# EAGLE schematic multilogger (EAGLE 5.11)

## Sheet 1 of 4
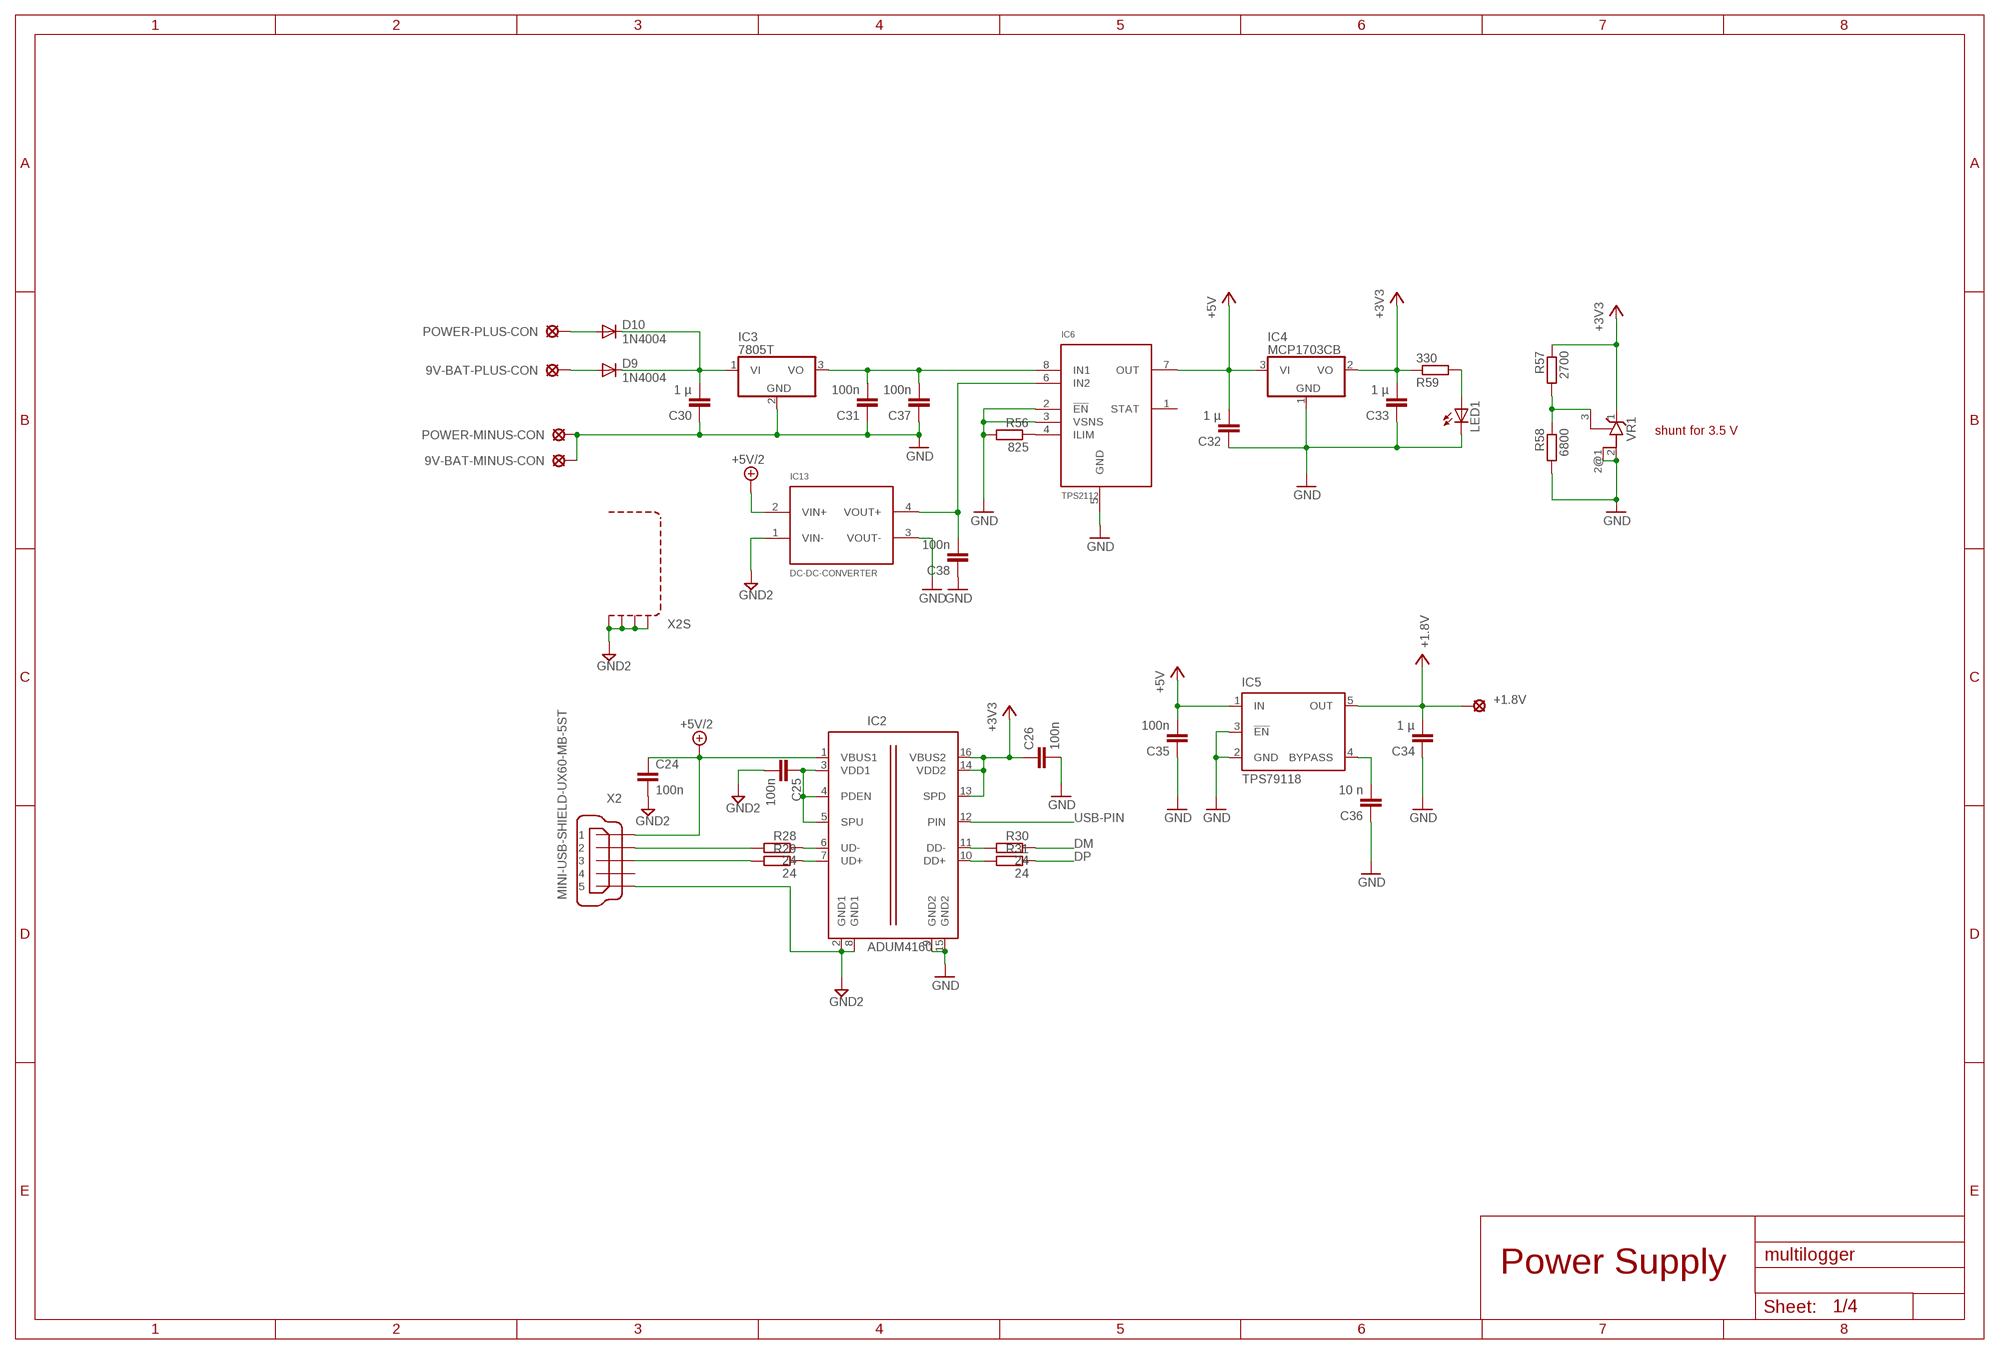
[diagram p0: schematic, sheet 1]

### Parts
9V-BAT-MINUS-CON  LSP10  [LSP10]
9V-BAT-PLUS-CON  LSP10  [LSP10]
+1.8V  LSP10  [LSP10]
C24  100n  C-EUC0805  [C0805]
C25  100n  C-EUC0805  [C0805]
C26  100n  C-EUC0805  [C0805]
C30  1 µ  C-EUC0805  [C0805]
C31  100n  C-EUC0805  [C0805]
C32  1 µ  C-EUC0805  [C0805]
C33  1 µ  C-EUC0805  [C0805]
C34  1 µ  C-EUC0805  [C0805]
C35  100n  C-EUC0805  [C0805]
C36  10 n  C-EUC0805  [C0805]
C37  100n  C-EUC0805  [C0805]
C38  100n  C-EUC0805  [C0805]
D9  1N4004  [DO41-10]
D10  1N4004  [DO41-10]
IC2  ADUM4160  [SO-16W]
IC3  7805T  [TO220H]
IC4  MCP1703CB  [SOT23]
IC5  TPS79118  [SOT23-DBV]
IC6  TPS2112  [TSSOP8]
IC13  DC-DC-CONVERTER  [DC-DC-CONVERTER]
LED1  LED5MM  [LED5MM]
POWER-MINUS-CON  LSP10  [LSP10]
POWER-PLUS-CON  LSP10  [LSP10]
R28  24  R-EU_R0805  [R0805]
R29  24  R-EU_R0805  [R0805]
R30  24  R-EU_R0805  [R0805]
R31  24  R-EU_R0805  [R0805]
R56  825  R-EU_R0805  [R0805]
R57  2700  R-EU_R0805  [R0805]
R58  6800  R-EU_R0805  [R0805]
R59  330  R-EU_R0805  [R0805]
VR1  TL431CLPSO89-3  [SOT89]
X2  MINI-USB-SHIELD-UX60-MB-5ST  [TYCO]

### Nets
+1.8V: +1.8V.MP C34.2 IC5.5(OUT) ; also sheet 4
+3V3: C26.1 C33.2 IC2.13(SPD) IC2.14(VDD2) IC2.16(VBUS2) IC4.2(VO) R57.1 R59.1 VR1.1(C) ; also sheet 2,3,4
+5V: C32.2 C35.2 IC4.3(VI) IC5.1(IN) IC6.7(OUT) ; also sheet 2
+5V/2: C24.1 IC2.1(VBUS1) IC13.2(VIN+) X2.1
DM: R30.1 ; also sheet 2
DP: R31.1 ; also sheet 2
GND: 9V-BAT-MINUS-CON.MP C26.2 C30.1 C31.1 C32.1 C33.1 C34.1 C35.1 C36.1 C37.1 C38.1 IC2.9(GND2) IC2.15(GND2) IC3.2(GND) IC4.1(GND) IC5.2(GND) IC5.3(!EN) IC6.2(!EN) IC6.3(VSNS) IC6.5(GND) IC13.3(VOUT-) LED1.K(C) POWER-MINUS-CON.MP R56.2 R58.2 VR1.2(A) VR1.2@1(A1) ; also sheet 2,3,4
GND2: C24.2 C25.2 IC2.2(GND1) IC2.8(GND1) IC13.1(VIN-) X2.5 X2.M1(S1) X2.M2(S2) X2.M3(S3) X2.M4(S4)
N$20: LED1.A R59.2
N$38: R28.2 X2.2
N$41: R29.2 X2.3
N$43: C25.1 IC2.3(VDD1) IC2.4(PDEN) IC2.5(SPU)
N$53: IC2.6(UD-) R28.1
N$54: IC2.7(UD+) R29.1
N$57: IC2.11(DD-) R30.2
N$59: IC2.10(DD+) R31.2
N$101: 9V-BAT-PLUS-CON.MP D9.A
N$102: D10.A POWER-PLUS-CON.MP
N$104: C36.2 IC5.4(BYPASS)
N$105: C30.2 D9.C D10.C IC3.1(VI)
N$106: C31.2 C37.2 IC3.3(VO) IC6.8(IN1)
N$108: C38.2 IC6.6(IN2) IC13.4(VOUT+)
N$109: IC6.4(ILIM) R56.1
N$110: R57.2 R58.1 VR1.3(R)
USB-PIN: IC2.12(PIN) ; also sheet 2
Unconnected: IC6.1(STAT) X2.4

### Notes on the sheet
- shunt for 3.5 V
- Power Supply

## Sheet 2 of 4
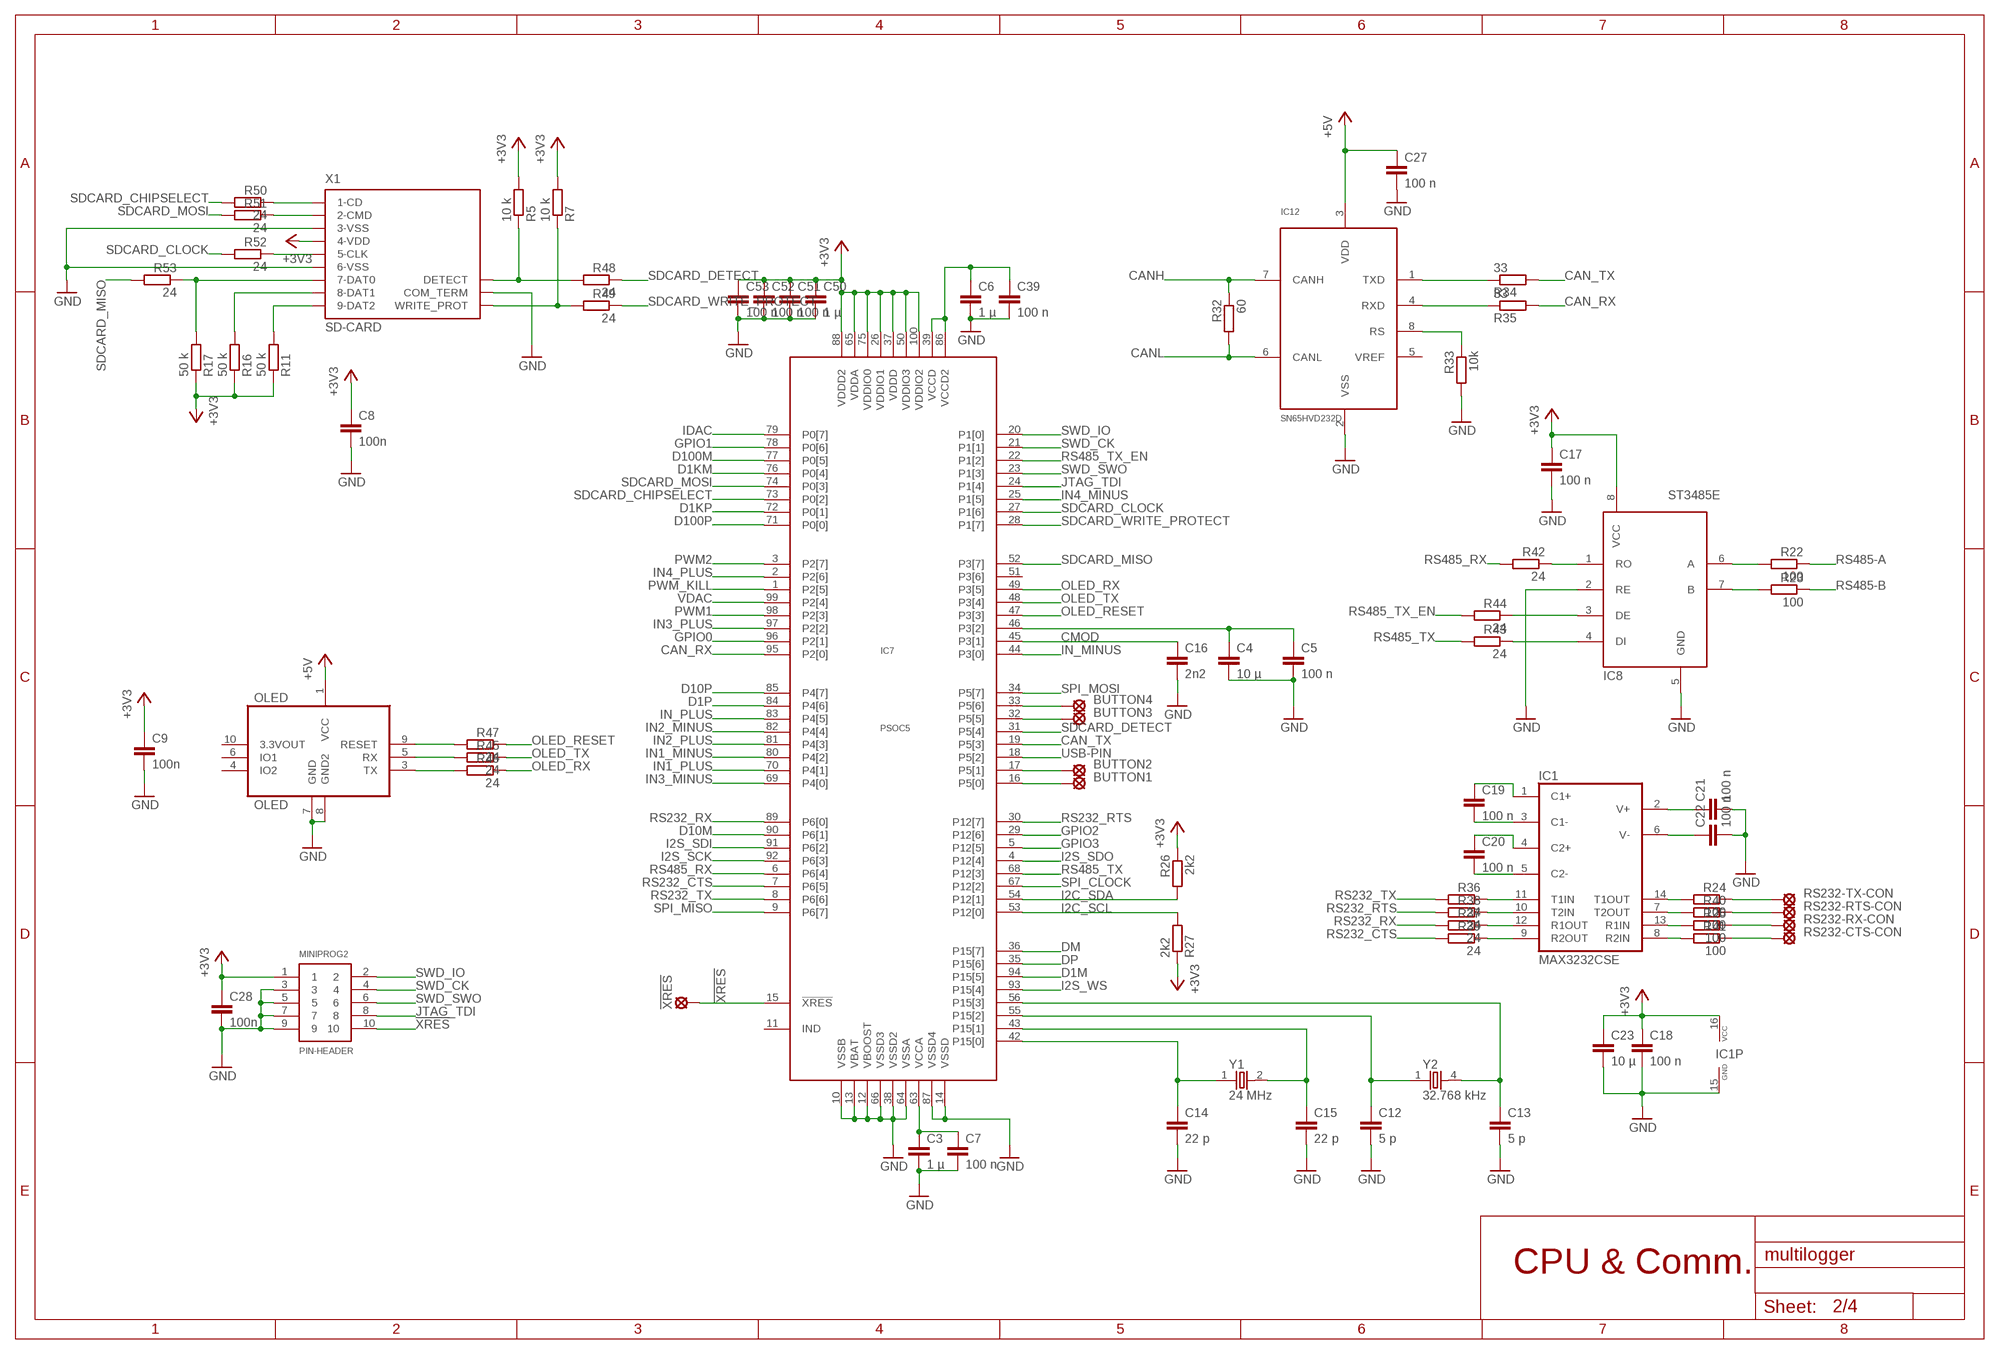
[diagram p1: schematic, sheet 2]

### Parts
!XRES  LSP10  [LSP10]
BUTTON1  LSP10  [LSP10]
BUTTON2  LSP10  [LSP10]
BUTTON3  LSP10  [LSP10]
BUTTON4  LSP10  [LSP10]
C3  1 µ  C-EUC0805  [C0805]
C4  10 µ  C-EUC0805  [C0805]
C5  100 n  C-EUC0805  [C0805]
C6  1 µ  C-EUC0805  [C0805]
C7  100 n  C-EUC0805  [C0805]
C8  100n  C-EUC0805  [C0805]
C9  100n  C-EUC0805  [C0805]
C12  5 p  C-EUC0805  [C0805]
C13  5 p  C-EUC0805  [C0805]
C14  22 p  C-EUC0805  [C0805]
C15  22 p  C-EUC0805  [C0805]
C16  2n2  C-EUC0805  [C0805]
C17  100 n  C-EUC0805  [C0805]
C18  100 n  C-EUC0805  [C0805]
C19  100 n  C-EUC0805  [C0805]
C20  100 n  C-EUC0805  [C0805]
C21  100 n  C-EUC0805  [C0805]
C22  100 n  C-EUC0805  [C0805]
C23  10 µ  C-EUC0805  [C0805]
C27  100 n  C-EUC0805  [C0805]
C28  100n  C-EUC0805  [C0805]
C39  100 n  C-EUC0805  [C0805]
C50  1 µ  C-EUC0805  [C0805]
C51  100 n  C-EUC0805  [C0805]
C52  100 n  C-EUC0805  [C0805]
C53  100 n  C-EUC0805  [C0805]
IC1  MAX3232CSE  [SO16]
IC7  PSOC5  [TQFP100]
IC8  ST3485E  [SO08]
IC12  SN65HVD232D  MCP2551SOIC8  [SOIC8]
MINIPROG2  PIN-HEADER  [PIN-HEADER-50-MIL-2X5]
OLED  OLED  [MA05-2]
R5  10 k  R-EU_R0805  [R0805]
R7  10 k  R-EU_R0805  [R0805]
R11  50 k  R-EU_R0805  [R0805]
R16  50 k  R-EU_R0805  [R0805]
R17  50 k  R-EU_R0805  [R0805]
R22  100  R-EU_R0805  [R0805]
R23  100  R-EU_R0805  [R0805]
R24  100  R-EU_R0805  [R0805]
R25  100  R-EU_R0805  [R0805]
R26  2k2  R-EU_R0805  [R0805]
R27  2k2  R-EU_R0805  [R0805]
R32  60  R-EU_0207/5V  [0207/5V]
R33  10k  R-EU_R0805  [R0805]
R34  33  R-EU_R0805  [R0805]
R35  33  R-EU_R0805  [R0805]
R36  24  R-EU_R0805  [R0805]
R37  24  R-EU_R0805  [R0805]
R38  24  R-EU_R0805  [R0805]
R39  24  R-EU_R0805  [R0805]
R40  100  R-EU_R0805  [R0805]
R41  100  R-EU_R0805  [R0805]
R42  24  R-EU_R0805  [R0805]
R43  24  R-EU_R0805  [R0805]
R44  24  R-EU_R0805  [R0805]
R45  24  R-EU_R0805  [R0805]
R46  24  R-EU_R0805  [R0805]
R47  24  R-EU_R0805  [R0805]
R48  24  R-EU_R0805  [R0805]
R49  24  R-EU_R0805  [R0805]
R50  24  R-EU_R0805  [R0805]
R51  24  R-EU_R0805  [R0805]
R52  24  R-EU_R0805  [R0805]
R53  24  R-EU_R0805  [R0805]
RS232-CTS-CON  LSP10  [LSP10]
RS232-RTS-CON  LSP10  [LSP10]
RS232-RX-CON  LSP10  [LSP10]
RS232-TX-CON  LSP10  [LSP10]
X1  SD-CARD  FPS009-3000  [FPS009-3000]
Y1  24 MHz  ECS-CRYSTAL  [ECS-CRYSTAL]
Y2  32.768 kHz  ABS25-CRYSTAL  [ABS25-CRYSTAL]

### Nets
!XRES: !XRES.MP IC7.15(!XRES) MINIPROG2.10
+3V3: C8.1 C9.1 C17.1 C18.1 C23.1 C28.1 C50.1 C51.1 C52.1 C53.1 IC1.16(VCC) IC7.26(VDDIO1) IC7.37(VDDD) IC7.50(VDDIO3) IC7.65(VDDA) IC7.75(VDDIO0) IC7.88(VDDD2) IC7.100(VDDIO2) IC8.8(VCC) MINIPROG2.1 R5.2 R7.2 R11.1 R16.1 R17.1 R26.1 R27.1 X1.4(4-VDD) ; also sheet 1,3,4
+5V: C27.1 IC12.3(VDD) OLED.1(VCC) ; also sheet 1
CAN_RX: IC7.95(P2[0]) R35.2
CAN_TX: IC7.19(P5[3]) R34.2
CANH: IC12.7(CANH) R32.1 ; also sheet 4
CANL: IC12.6(CANL) R32.2 ; also sheet 4
CMOD: C16.1 IC7.45(P3[1])
D1KM: IC7.76(P0[4]) ; also sheet 3
D1KP: IC7.72(P0[1]) ; also sheet 3
D1M: IC7.94(P15[5]) ; also sheet 3
D1P: IC7.84(P4[6]) ; also sheet 3
D10M: IC7.90(P6[1]) ; also sheet 3
D10P: IC7.85(P4[7]) ; also sheet 3
D100M: IC7.77(P0[5]) ; also sheet 3
D100P: IC7.71(P0[0]) ; also sheet 3
DM: IC7.36(P15[7]) ; also sheet 1
DP: IC7.35(P15[6]) ; also sheet 1
GND: C3.2 C4.2 C5.2 C6.2 C7.2 C8.2 C9.2 C12.2 C13.2 C14.2 C15.2 C16.2 C17.2 C18.2 C21.2 C22.2 C23.2 C27.2 C28.2 C39.2 C50.2 C51.2 C52.2 C53.2 IC1.15(GND) IC7.10(VSSB) IC7.12(VBOOST) IC7.13(VBAT) IC7.14(VSSD) IC7.38(VSSD2) IC7.64(VSSA) IC7.66(VSSD3) IC7.87(VSSD4) IC8.2(RE) IC8.5(GND) IC12.2(VSS) MINIPROG2.3 MINIPROG2.5 MINIPROG2.7 MINIPROG2.9 OLED.7(GND) OLED.8(GND2) R33.2 X1.3(3-VSS) X1.6(6-VSS) X1.COM_TERM ; also sheet 1,3,4
GPIO0: IC7.96(P2[1]) ; also sheet 4
GPIO1: IC7.78(P0[6]) ; also sheet 4
GPIO2: IC7.29(P12[6]) ; also sheet 4
GPIO3: IC7.5(P12[5]) ; also sheet 4
I2C_SCL: IC7.53(P12[0]) R27.2 ; also sheet 4
I2C_SDA: IC7.54(P12[1]) R26.2 ; also sheet 4
I2S_SCK: IC7.92(P6[3]) ; also sheet 4
I2S_SDI: IC7.91(P6[2]) ; also sheet 4
I2S_SDO: IC7.4(P12[4]) ; also sheet 4
I2S_WS: IC7.93(P15[4]) ; also sheet 4
IDAC: IC7.79(P0[7]) ; also sheet 4
IN1_MINUS: IC7.80(P4[2]) ; also sheet 3
IN1_PLUS: IC7.70(P4[1]) ; also sheet 3
IN2_MINUS: IC7.82(P4[4]) ; also sheet 3
IN2_PLUS: IC7.81(P4[3]) ; also sheet 3
IN3_MINUS: IC7.69(P4[0]) ; also sheet 3
IN3_PLUS: IC7.97(P2[2]) ; also sheet 3
IN4_MINUS: IC7.25(P1[5]) ; also sheet 3
IN4_PLUS: IC7.2(P2[6]) ; also sheet 3
IN_MINUS: IC7.44(P3[0]) ; also sheet 3
IN_PLUS: IC7.83(P4[5]) ; also sheet 3
JTAG_TDI: IC7.24(P1[4]) MINIPROG2.8
N$3: IC12.8(RS) R33.1
N$7: IC8.6(A) R22.2
N$8: IC8.7(B) R23.2
N$9: R11.2 X1.9(9-DAT2)
N$13: C19.1 IC1.1(C1+)
N$14: IC12.1(TXD) R34.1
N$15: IC12.4(RXD) R35.1
N$16: C3.1 C7.1 IC7.63(VCCA)
N$18: C19.2 IC1.3(C1-)
N$21: C4.1 C5.1 IC7.46(P3[2])
N$22: C6.1 C39.1 IC7.39(VCCD) IC7.86(VCCD2)
N$23: IC1.10(T2IN) R38.1
N$24: R16.2 X1.8(8-DAT1)
N$27: C20.1 IC1.4(C2+)
N$28: C20.2 IC1.5(C2-)
N$31: C21.1 IC1.2(V+)
N$32: C22.1 IC1.6(V-)
N$33: IC1.14(T1OUT) R24.2
N$34: IC1.13(R1IN) R25.2
N$35: R24.1 RS232-TX-CON.MP
N$36: R25.1 RS232-RX-CON.MP
N$37: IC1.11(T1IN) R36.1
N$39: IC1.12(R1OUT) R37.1
N$40: IC1.9(R2OUT) R39.1
N$44: IC1.7(T2OUT) R40.2
N$45: IC1.8(R2IN) R41.2
N$46: BUTTON4.MP IC7.33(P5[6])
N$47: BUTTON3.MP IC7.32(P5[5])
N$48: R40.1 RS232-RTS-CON.MP
N$49: R41.1 RS232-CTS-CON.MP
N$50: IC8.4(DI) R43.1
N$51: BUTTON2.MP IC7.17(P5[1])
N$52: BUTTON1.MP IC7.16(P5[0])
N$55: IC8.1(RO) R42.1
N$56: IC8.3(DE) R44.1
N$58: OLED.5(RX) R45.2
N$60: R17.2 R53.1 X1.7(7-DAT0)
N$61: OLED.9(RESET) R47.2
N$62: OLED.3(TX) R46.2
N$63: R52.1 X1.5(5-CLK)
N$64: R51.1 X1.2(2-CMD)
N$65: R50.1 X1.1(1-CD)
N$66: R5.1 R48.2 X1.DETECT
N$67: R7.1 R49.2 X1.WRITE_PROT
N$73: C13.1 IC7.56(P15[3]) Y2.4
N$74: C12.1 IC7.55(P15[2]) Y2.1
N$75: C15.1 IC7.43(P15[1]) Y1.2
N$76: C14.1 IC7.42(P15[0]) Y1.1
OLED_RESET: IC7.47(P3[3]) R47.1
OLED_RX: IC7.49(P3[5]) R46.1
OLED_TX: IC7.48(P3[4]) R45.1
PWM1: IC7.98(P2[3]) ; also sheet 4
PWM2: IC7.3(P2[7]) ; also sheet 4
PWM_KILL: IC7.1(P2[5]) ; also sheet 4
RS232_CTS: IC7.7(P6[5]) R39.2
RS232_RTS: IC7.30(P12[7]) R38.2
RS232_RX: IC7.89(P6[0]) R37.2
RS232_TX: IC7.8(P6[6]) R36.2
RS485-A: R22.1 ; also sheet 4
RS485-B: R23.1 ; also sheet 4
RS485_RX: IC7.6(P6[4]) R42.2
RS485_TX: IC7.68(P12[3]) R43.2
RS485_TX_EN: IC7.22(P1[2]) R44.2
SDCARD_CHIPSELECT: IC7.73(P0[2]) R50.2
SDCARD_CLOCK: IC7.27(P1[6]) R52.2
SDCARD_DETECT: IC7.31(P5[4]) R48.1
SDCARD_MISO: IC7.52(P3[7]) R53.2
SDCARD_MOSI: IC7.74(P0[3]) R51.2
SDCARD_WRITE_PROTECT: IC7.28(P1[7]) R49.1
SPI_CLOCK: IC7.67(P12[2]) ; also sheet 4
SPI_MISO: IC7.9(P6[7]) ; also sheet 4
SPI_MOSI: IC7.34(P5[7]) ; also sheet 4
SWD_CK: IC7.21(P1[1]) MINIPROG2.4
SWD_IO: IC7.20(P1[0]) MINIPROG2.2
SWD_SWO: IC7.23(P1[3]) MINIPROG2.6
USB-PIN: IC7.18(P5[2]) ; also sheet 1
VDAC: IC7.99(P2[4]) ; also sheet 4
Unconnected: IC7.11(IND) IC7.51(P3[6]) IC12.5(VREF) OLED.4(IO2) OLED.6(IO1) OLED.10(3.3VOUT)

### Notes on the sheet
- CPU & Comm.

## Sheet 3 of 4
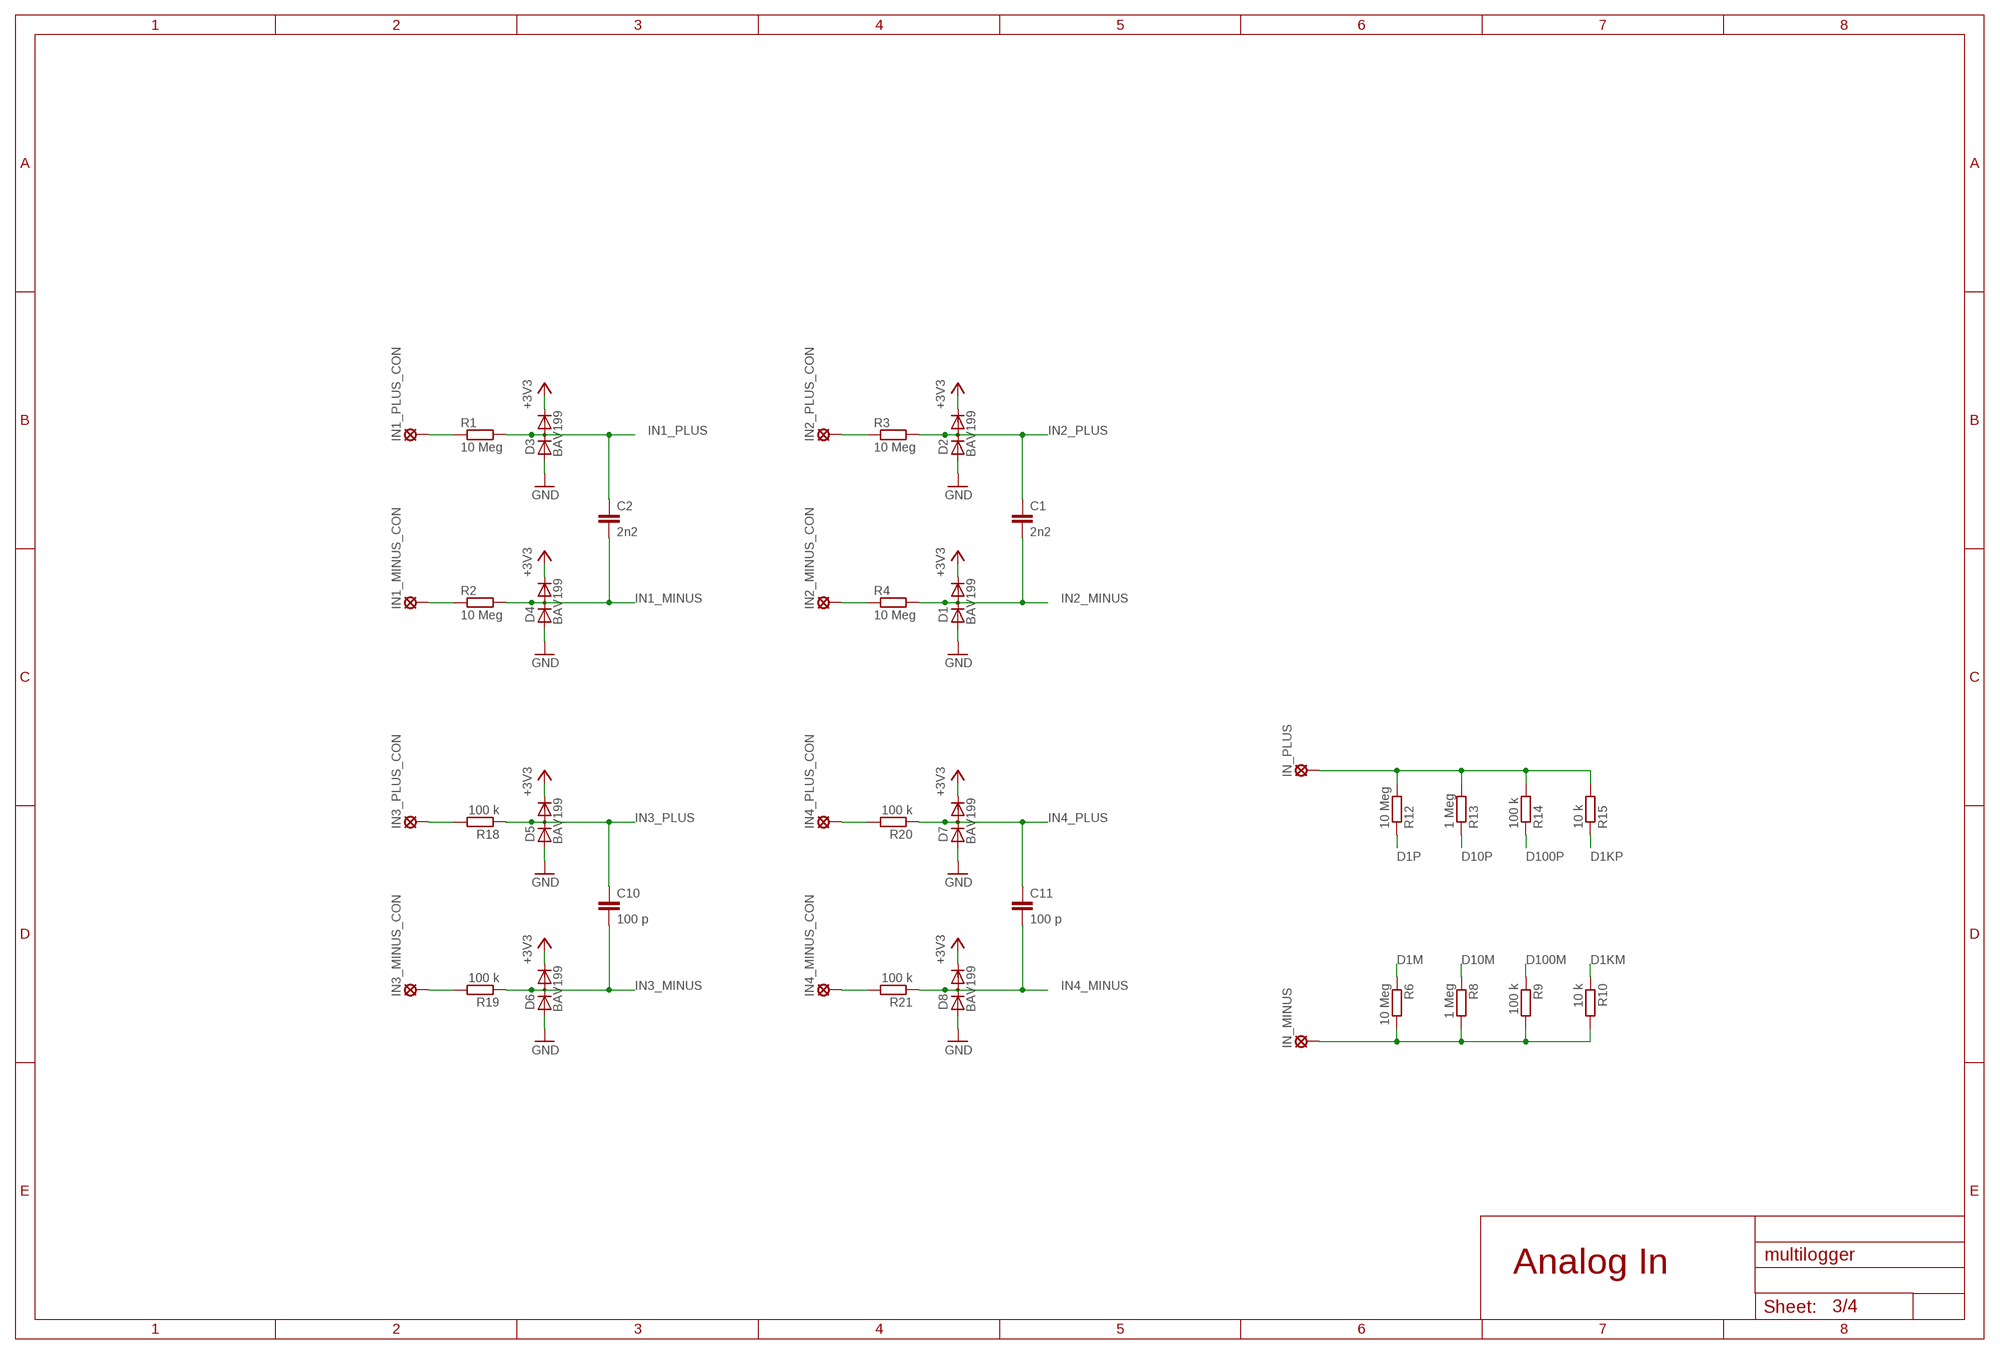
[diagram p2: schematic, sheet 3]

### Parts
C1  2n2  C-EUC0805  [C0805]
C2  2n2  C-EUC0805  [C0805]
C10  100 p  C-EUC0805  [C0805]
C11  100 p  C-EUC0805  [C0805]
D1  BAV199  [SOT23]
D2  BAV199  [SOT23]
D3  BAV199  [SOT23]
D4  BAV199  [SOT23]
D5  BAV199  [SOT23]
D6  BAV199  [SOT23]
D7  BAV199  [SOT23]
D8  BAV199  [SOT23]
IN1_MINUS_CON  LSP10  [LSP10]
IN1_PLUS_CON  LSP10  [LSP10]
IN2_MINUS_CON  LSP10  [LSP10]
IN2_PLUS_CON  LSP10  [LSP10]
IN3_MINUS_CON  LSP10  [LSP10]
IN3_PLUS_CON  LSP10  [LSP10]
IN4_MINUS_CON  LSP10  [LSP10]
IN4_PLUS_CON  LSP10  [LSP10]
IN_MINUS  LSP10  [LSP10]
IN_PLUS  LSP10  [LSP10]
R1  10 Meg  R-EU_0207/15  [0207/35]
R2  10 Meg  R-EU_0207/15  [0207/35]
R3  10 Meg  R-EU_0207/15  [0207/35]
R4  10 Meg  R-EU_0207/15  [0207/35]
R6  10 Meg  R-EU_R1206  [R1206]
R8  1 Meg  R-EU_R1206  [R1206]
R9  100 k  R-EU_R1206  [R1206]
R10  10 k  R-EU_R1206  [R1206]
R12  10 Meg  R-EU_R1206  [R1206]
R13  1 Meg  R-EU_R1206  [R1206]
R14  100 k  R-EU_R1206  [R1206]
R15  10 k  R-EU_R1206  [R1206]
R18  100 k  R-EU_R1206  [R1206]
R19  100 k  R-EU_R1206  [R1206]
R20  100 k  R-EU_R1206  [R1206]
R21  100 k  R-EU_R1206  [R1206]

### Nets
+3V3: D1.2(C) D2.2(C) D3.2(C) D4.2(C) D5.2(C) D6.2(C) D7.2(C) D8.2(C) ; also sheet 1,2,4
D1KM: R10.1 ; also sheet 2
D1KP: R15.1 ; also sheet 2
D1M: R6.1 ; also sheet 2
D1P: R12.1 ; also sheet 2
D10M: R8.1 ; also sheet 2
D10P: R13.1 ; also sheet 2
D100M: R9.1 ; also sheet 2
D100P: R14.1 ; also sheet 2
GND: D1.1(A) D2.1(A) D3.1(A) D4.1(A) D5.1(A) D6.1(A) D7.1(A) D8.1(A) ; also sheet 1,2,4
IN1_MINUS: C2.2 D4.3(AC) R2.2 ; also sheet 2
IN1_PLUS: C2.1 D3.3(AC) R1.2 ; also sheet 2
IN2_MINUS: C1.2 D1.3(AC) R4.2 ; also sheet 2
IN2_PLUS: C1.1 D2.3(AC) R3.2 ; also sheet 2
IN3_MINUS: C10.2 D6.3(AC) R19.1 ; also sheet 2
IN3_PLUS: C10.1 D5.3(AC) R18.1 ; also sheet 2
IN4_MINUS: C11.2 D8.3(AC) R21.1 ; also sheet 2
IN4_PLUS: C11.1 D7.3(AC) R20.1 ; also sheet 2
IN_MINUS: IN_MINUS.MP R6.2 R8.2 R9.2 R10.2 ; also sheet 2
IN_PLUS: IN_PLUS.MP R12.2 R13.2 R14.2 R15.2 ; also sheet 2
N$1: IN2_PLUS_CON.MP R3.1
N$2: IN2_MINUS_CON.MP R4.1
N$5: IN1_PLUS_CON.MP R1.1
N$6: IN1_MINUS_CON.MP R2.1
N$25: IN3_PLUS_CON.MP R18.2
N$26: IN3_MINUS_CON.MP R19.2
N$29: IN4_PLUS_CON.MP R20.2
N$30: IN4_MINUS_CON.MP R21.2

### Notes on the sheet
- Analog In

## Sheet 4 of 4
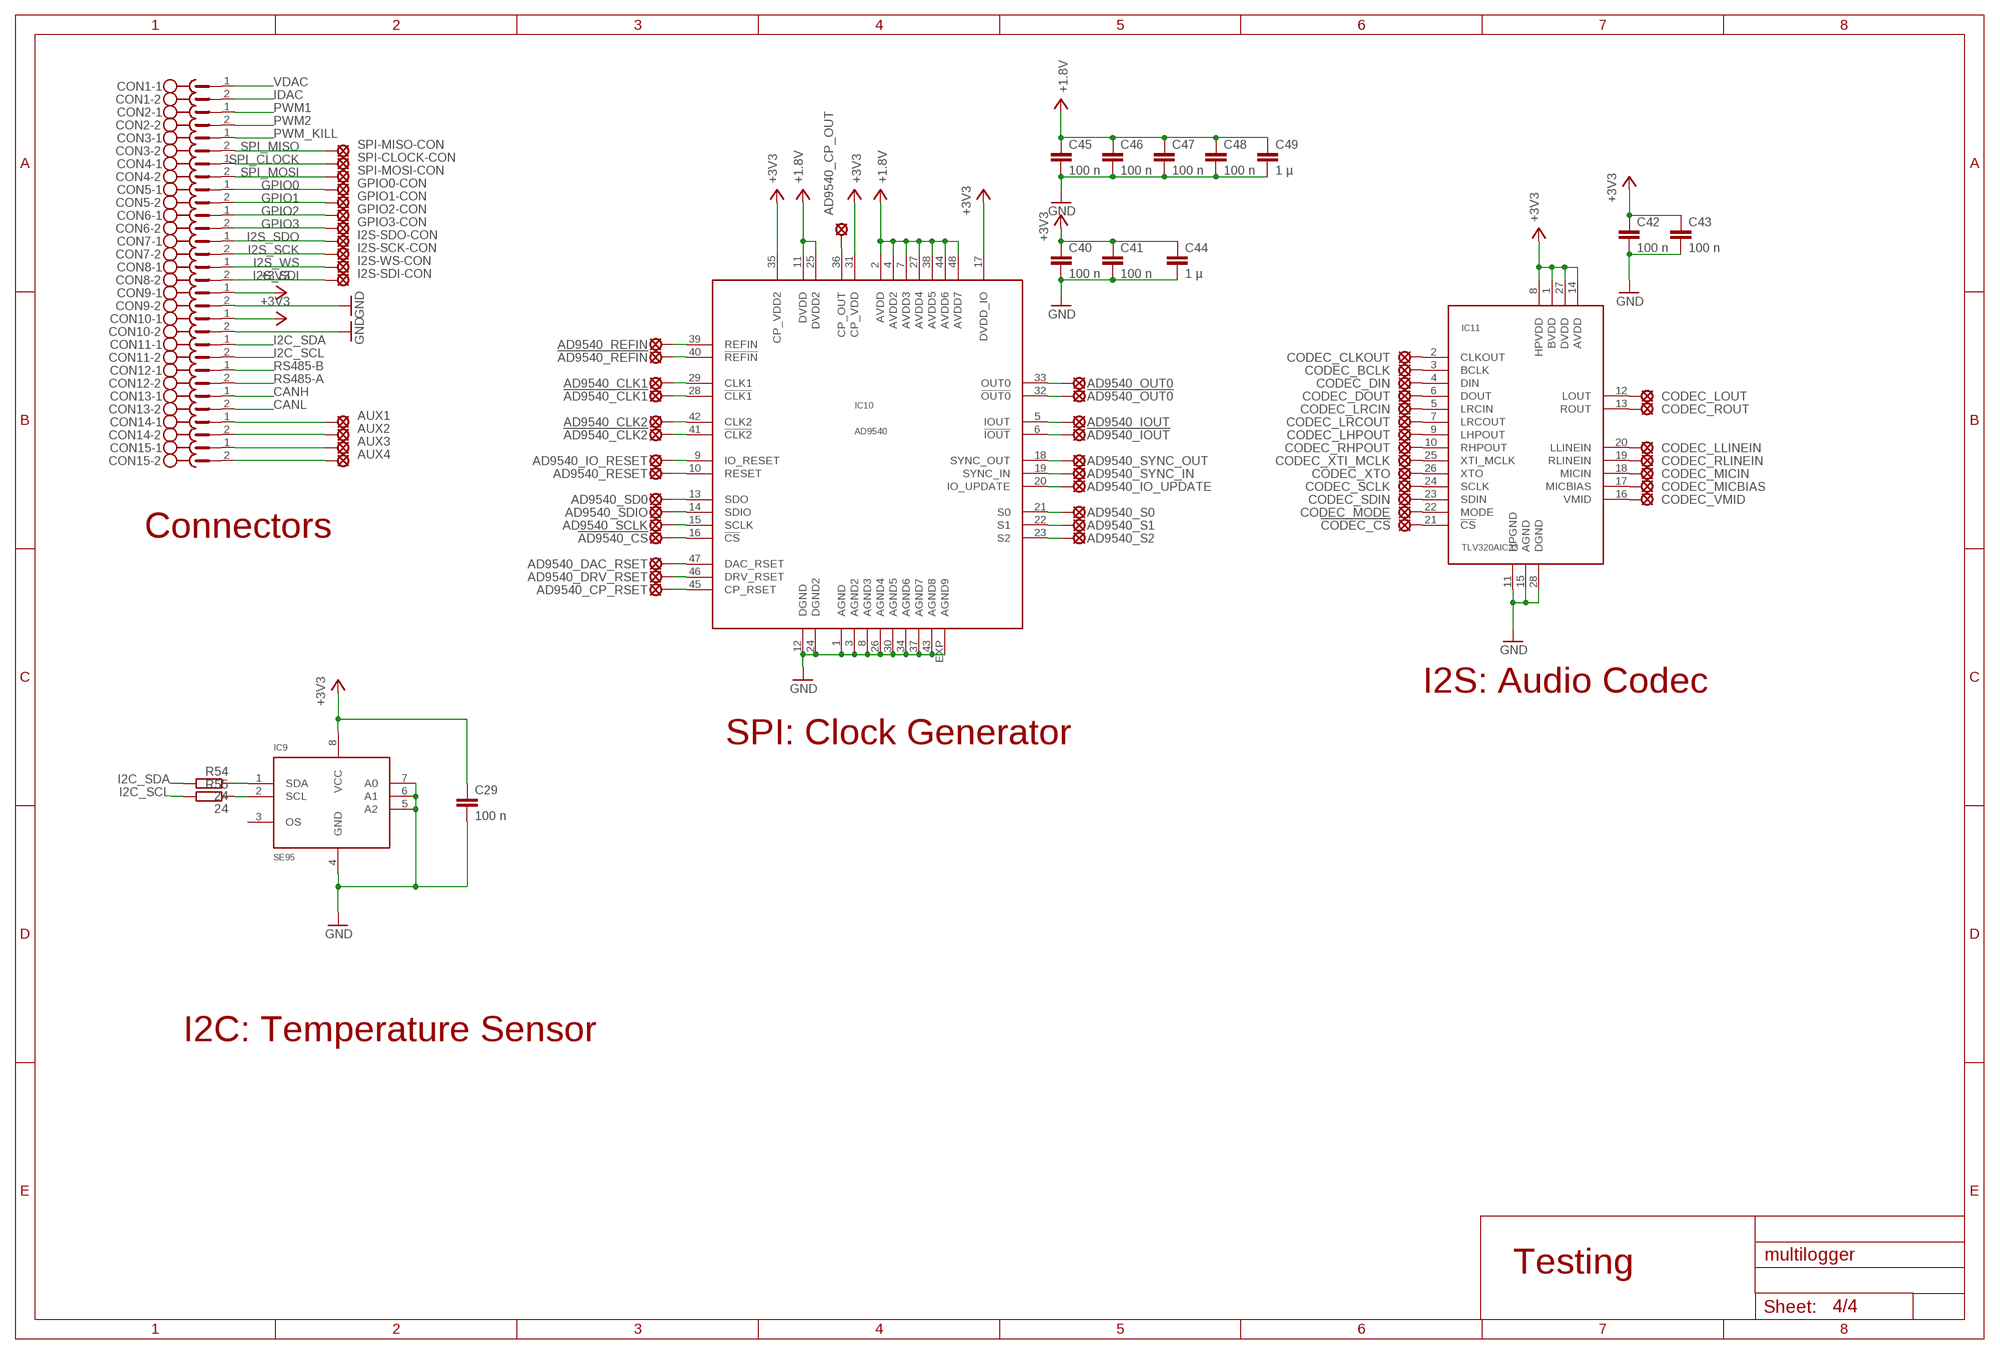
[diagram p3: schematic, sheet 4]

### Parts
!AD9540_CLK1  LSP10  [LSP10]
!AD9540_CLK2  LSP10  [LSP10]
!AD9540_CS  LSP10  [LSP10]
!AD9540_IOUT  LSP10  [LSP10]
!AD9540_OUT0  LSP10  [LSP10]
!AD9540_REFIN  LSP10  [LSP10]
!CODEC_CS  LSP10  [LSP10]
AD9540_CLK1  LSP10  [LSP10]
AD9540_CLK2  LSP10  [LSP10]
AD9540_CP_OUT  LSP10  [LSP10]
AD9540_CP_RSET  LSP10  [LSP10]
AD9540_DAC_RSET  LSP10  [LSP10]
AD9540_DRV_RSET  LSP10  [LSP10]
AD9540_IO_RESET  LSP10  [LSP10]
AD9540_IO_UPDATE  LSP10  [LSP10]
AD9540_IOUT  LSP10  [LSP10]
AD9540_OUT0  LSP10  [LSP10]
AD9540_REFIN  LSP10  [LSP10]
AD9540_RESET  LSP10  [LSP10]
AD9540_S0  LSP10  [LSP10]
AD9540_S1  LSP10  [LSP10]
AD9540_S2  LSP10  [LSP10]
AD9540_SCLK  LSP10  [LSP10]
AD9540_SD0  LSP10  [LSP10]
AD9540_SDIO  LSP10  [LSP10]
AD9540_SYNC_IN  LSP10  [LSP10]
AD9540_SYNC_OUT  LSP10  [LSP10]
AUX1  LSP10  [LSP10]
AUX2  LSP10  [LSP10]
AUX3  LSP10  [LSP10]
AUX4  LSP10  [LSP10]
C29  100 n  C-EUC0805  [C0805]
C40  100 n  C-EUC0805  [C0805]
C41  100 n  C-EUC0805  [C0805]
C42  100 n  C-EUC0805  [C0805]
C43  100 n  C-EUC0805  [C0805]
C44  1 µ  C-EUC0805  [C0805]
C45  100 n  C-EUC0805  [C0805]
C46  100 n  C-EUC0805  [C0805]
C47  100 n  C-EUC0805  [C0805]
C48  100 n  C-EUC0805  [C0805]
C49  1 µ  C-EUC0805  [C0805]
CODEC_BCLK  LSP10  [LSP10]
CODEC_CLKOUT  LSP10  [LSP10]
CODEC_DIN  LSP10  [LSP10]
CODEC_DOUT  LSP10  [LSP10]
CODEC_LHPOUT  LSP10  [LSP10]
CODEC_LLINEIN  LSP10  [LSP10]
CODEC_LOUT  LSP10  [LSP10]
CODEC_LRCIN  LSP10  [LSP10]
CODEC_LRCOUT  LSP10  [LSP10]
CODEC_MICBIAS  LSP10  [LSP10]
CODEC_MICIN  LSP10  [LSP10]
CODEC_MODE  LSP10  [LSP10]
CODEC_RHPOUT  LSP10  [LSP10]
CODEC_RLINEIN  LSP10  [LSP10]
CODEC_ROUT  LSP10  [LSP10]
CODEC_SCLK  LSP10  [LSP10]
CODEC_SDIN  LSP10  [LSP10]
CODEC_VMID  LSP10  [LSP10]
CODEC_XTI_MCLK  LSP10  [LSP10]
CODEC_XTO  LSP10  [LSP10]
CON1  MSTBV2  [MSTBV2]
CON2  MSTBV2  [MSTBV2]
CON3  MSTBV2  [MSTBV2]
CON4  MSTBV2  [MSTBV2]
CON5  MSTBV2  [MSTBV2]
CON6  MSTBV2  [MSTBV2]
CON7  MSTBV2  [MSTBV2]
CON8  MSTBV2  [MSTBV2]
CON9  MSTBV2  [MSTBV2]
CON10  MSTBV2  [MSTBV2]
CON11  MSTBV2  [MSTBV2]
CON12  MSTBV2  [MSTBV2]
CON13  MSTBV2  [MSTBV2]
CON14  MSTBV2  [MSTBV2]
CON15  MSTBV2  [MSTBV2]
GPIO0-CON  LSP10  [LSP10]
GPIO1-CON  LSP10  [LSP10]
GPIO2-CON  LSP10  [LSP10]
GPIO3-CON  LSP10  [LSP10]
I2S-SCK-CON  LSP10  [LSP10]
I2S-SDI-CON  LSP10  [LSP10]
I2S-SDO-CON  LSP10  [LSP10]
I2S-WS-CON  LSP10  [LSP10]
IC9  SE95  [TSSOP8]
IC10  AD9540  [LFCSP48]
IC11  TLV320AIC23  [TSSOP28]
R54  24  R-EU_R0805  [R0805]
R55  24  R-EU_R0805  [R0805]
SPI-CLOCK-CON  LSP10  [LSP10]
SPI-MISO-CON  LSP10  [LSP10]
SPI-MOSI-CON  LSP10  [LSP10]

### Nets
+1.8V: C45.1 C46.1 C47.1 C48.1 C49.1 IC10.2(AVDD) IC10.4(AVDD2) IC10.7(AVDD3) IC10.11(DVDD) IC10.25(DVDD2) IC10.27(AVDD4) IC10.38(AVDD5) IC10.44(AVDD6) IC10.48(AVDD7) ; also sheet 1
+3V3: C29.1 C40.1 C41.1 C42.1 C43.1 C44.1 CON9.1 CON10.1 IC9.8(VCC) IC10.17(DVDD_IO) IC10.31(CP_VDD) IC10.35(CP_VDD2) IC11.1(BVDD) IC11.8(HPVDD) IC11.14(AVDD) IC11.27(DVDD) ; also sheet 1,2,3
CANH: CON13.1 ; also sheet 2
CANL: CON13.2 ; also sheet 2
GND: C29.2 C40.2 C41.2 C42.2 C43.2 C44.2 C45.2 C46.2 C47.2 C48.2 C49.2 CON9.2 CON10.2 IC9.4(GND) IC9.5(A2) IC9.6(A1) IC9.7(A0) IC10.1(AGND) IC10.3(AGND2) IC10.8(AGND3) IC10.12(DGND) IC10.24(DGND2) IC10.26(AGND4) IC10.30(AGND5) IC10.34(AGND6) IC10.37(AGND7) IC10.43(AGND8) IC10.EXP(AGND9) IC11.11(HPGND) IC11.15(AGND) IC11.28(DGND) ; also sheet 1,2,3
GPIO0: CON5.1 GPIO0-CON.MP ; also sheet 2
GPIO1: CON5.2 GPIO1-CON.MP ; also sheet 2
GPIO2: CON6.1 GPIO2-CON.MP ; also sheet 2
GPIO3: CON6.2 GPIO3-CON.MP ; also sheet 2
I2C_SCL: CON11.2 R55.2 ; also sheet 2
I2C_SDA: CON11.1 R54.2 ; also sheet 2
I2S_SCK: CON7.2 I2S-SCK-CON.MP ; also sheet 2
I2S_SDI: CON8.2 I2S-SDI-CON.MP ; also sheet 2
I2S_SDO: CON7.1 I2S-SDO-CON.MP ; also sheet 2
I2S_WS: CON8.1 I2S-WS-CON.MP ; also sheet 2
IDAC: CON1.2 ; also sheet 2
N$4: AUX1.MP CON14.1
N$10: AUX2.MP CON14.2
N$11: AUX3.MP CON15.1
N$12: AUX4.MP CON15.2
N$68: IC9.1(SDA) R54.1
N$69: IC9.2(SCL) R55.1
N$70: AD9540_CP_OUT.MP IC10.36(CP_OUT)
N$71: AD9540_REFIN.MP IC10.39(REFIN)
N$77: !AD9540_REFIN.MP IC10.40(!REFIN)
N$78: AD9540_CLK1.MP IC10.29(CLK1)
N$79: !AD9540_CLK1.MP IC10.28(!CLK1)
N$80: AD9540_CLK2.MP IC10.42(CLK2)
N$81: !AD9540_CLK2.MP IC10.41(!CLK2)
N$82: AD9540_IO_RESET.MP IC10.9(IO_RESET)
N$83: AD9540_RESET.MP IC10.10(RESET)
N$84: AD9540_SD0.MP IC10.13(SDO)
N$85: AD9540_SDIO.MP IC10.14(SDIO)
N$86: AD9540_SCLK.MP IC10.15(SCLK)
N$87: !AD9540_CS.MP IC10.16(!CS)
N$88: AD9540_DAC_RSET.MP IC10.47(DAC_RSET)
N$89: AD9540_DRV_RSET.MP IC10.46(DRV_RSET)
N$90: AD9540_CP_RSET.MP IC10.45(CP_RSET)
N$91: AD9540_S2.MP IC10.23(S2)
N$92: AD9540_S1.MP IC10.22(S1)
N$93: AD9540_S0.MP IC10.21(S0)
N$94: AD9540_IO_UPDATE.MP IC10.20(IO_UPDATE)
N$95: AD9540_SYNC_IN.MP IC10.19(SYNC_IN)
N$96: AD9540_SYNC_OUT.MP IC10.18(SYNC_OUT)
N$97: !AD9540_IOUT.MP IC10.6(!IOUT)
N$98: AD9540_IOUT.MP IC10.5(IOUT)
N$99: !AD9540_OUT0.MP IC10.32(!OUT0)
N$100: AD9540_OUT0.MP IC10.33(OUT0)
N$107: CODEC_LRCOUT.MP IC11.7(LRCOUT)
N$111: CODEC_CLKOUT.MP IC11.2(CLKOUT)
N$112: CODEC_BCLK.MP IC11.3(BCLK)
N$113: CODEC_DIN.MP IC11.4(DIN)
N$114: CODEC_DOUT.MP IC11.6(DOUT)
N$115: CODEC_LRCIN.MP IC11.5(LRCIN)
N$116: CODEC_LHPOUT.MP IC11.9(LHPOUT)
N$117: CODEC_RHPOUT.MP IC11.10(RHPOUT)
N$118: CODEC_XTI_MCLK.MP IC11.25(XTI_MCLK)
N$119: CODEC_XTO.MP IC11.26(XTO)
N$120: CODEC_SCLK.MP IC11.24(SCLK)
N$121: CODEC_SDIN.MP IC11.23(SDIN)
N$122: CODEC_MODE.MP IC11.22(MODE)
N$123: !CODEC_CS.MP IC11.21(!CS)
N$124: CODEC_LOUT.MP IC11.12(LOUT)
N$125: CODEC_ROUT.MP IC11.13(ROUT)
N$126: CODEC_LLINEIN.MP IC11.20(LLINEIN)
N$127: CODEC_RLINEIN.MP IC11.19(RLINEIN)
N$128: CODEC_MICIN.MP IC11.18(MICIN)
N$129: CODEC_MICBIAS.MP IC11.17(MICBIAS)
N$130: CODEC_VMID.MP IC11.16(VMID)
PWM1: CON2.1 ; also sheet 2
PWM2: CON2.2 ; also sheet 2
PWM_KILL: CON3.1 ; also sheet 2
RS485-A: CON12.2 ; also sheet 2
RS485-B: CON12.1 ; also sheet 2
SPI_CLOCK: CON4.1 SPI-CLOCK-CON.MP ; also sheet 2
SPI_MISO: CON3.2 SPI-MISO-CON.MP ; also sheet 2
SPI_MOSI: CON4.2 SPI-MOSI-CON.MP ; also sheet 2
VDAC: CON1.1 ; also sheet 2
Unconnected: IC9.3(OS)

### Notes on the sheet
- Connectors
- I2S: Audio Codec
- SPI: Clock Generator
- I2C: Temperature Sensor
- Testing

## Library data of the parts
9V-BAT-MINUS-CON 9V-BAT-PLUS-CON !AD9540_CLK1 !AD9540_CLK2 !AD9540_CS !AD9540_IOUT !AD9540_OUT0 !AD9540_REFIN !CODEC_CS !XRES +1.8V AD9540_CLK1 AD9540_CLK2 AD9540_CP_OUT AD9540_CP_RSET AD9540_DAC_RSET AD9540_DRV_RSET AD9540_IO_RESET AD9540_IO_UPDATE AD9540_IOUT AD9540_OUT0 AD9540_REFIN AD9540_RESET AD9540_S0 AD9540_S1 AD9540_S2 AD9540_SCLK AD9540_SD0 AD9540_SDIO AD9540_SYNC_IN AD9540_SYNC_OUT AUX1-AUX4 BUTTON1-BUTTON4 CODEC_BCLK CODEC_CLKOUT CODEC_DIN CODEC_DOUT CODEC_LHPOUT CODEC_LLINEIN CODEC_LOUT CODEC_LRCIN CODEC_LRCOUT CODEC_MICBIAS CODEC_MICIN CODEC_MODE CODEC_RHPOUT CODEC_RLINEIN CODEC_ROUT CODEC_SCLK CODEC_SDIN CODEC_VMID CODEC_XTI_MCLK CODEC_XTO GPIO0-CON GPIO1-CON GPIO2-CON GPIO3-CON I2S-SCK-CON I2S-SDI-CON I2S-SDO-CON I2S-WS-CON IN1_MINUS_CON IN1_PLUS_CON IN2_MINUS_CON IN2_PLUS_CON IN3_MINUS_CON IN3_PLUS_CON IN4_MINUS_CON IN4_PLUS_CON IN_MINUS IN_PLUS POWER-MINUS-CON POWER-PLUS-CON RS232-CTS-CON RS232-RTS-CON RS232-RX-CON RS232-TX-CON SPI-CLOCK-CON SPI-MISO-CON SPI-MOSI-CON = solpad:LSP10: SOLDER PAD
C1-C53 = rcl:C-EU: CAPACITOR, European symbol
CON1-CON15 = con-phoenix-500:MSTBV2: PHOENIX; OC_FARNELL: unknown; OC_NEWARK: unknown
D1-D8 = diode:BAV199: DIODE low-leakage double diode
D9 D10 = diode:1N4004: DIODE
IC1 = maxim:MAX3232*: True RS-232 Transceivers 3.0V to 5.5V, Low-Power up to 1Mbps, Using Four 0.1µF External Capacitors Source: http://pdfserv.maxim-ic.com/en/ds/MAX3222-MAX3241.pdf; MPN: MAX3232CSE; OC_FARNELL: 9725490; OC_NEWARK: 90C2890
IC2 = parts:ADUM4160: Triple-Channel Digital Isolators Source: http://www.analog.com/static/imported-files/data_sheets/ADuM1300_1301.pdf
IC3 = linear:78*: Positive VOLTAGE REGULATOR Source: http://cache.national.com/ds/LM/LM78L05.pdf http://www.fairchildsemi.com/ds/LM/LM7805.pdf
IC4 = linear:MCP1703: 250 mA, 16V, Low Quiescent Current LDO Regulator Source: http://ww1.microchip.com/downloads/en/DeviceDoc/22049b.pdf
IC5 = parts:TPS79118: ULTRALOW-POWER 50-mA LOW-DROPOUT LINEAR REGULATORS 50-mA Low-Dropout Regulator Source: http://focus.ti.com/lit/ds/symlink/tps77001.pdf
IC6 = parts:TPS2112
IC7 = parts:PSOC5
IC8 = parts:ST3485E
IC9 = parts:SE95
IC10 = parts:AD9540
IC11 = parts:TLV320AIC23
IC12 = parts:MCP2551
IC13 = parts:DC-DC-CONVERTER
LED1 = led:LED: LED
MINIPROG2 = parts:PIN-HEADER
OLED = parts:OLED
R1-R4 = parts:R-EU_: RESISTOR, European symbol
R5-R59 = rcl:R-EU_: RESISTOR, European symbol
VR1 = parts:TL431CLP: VOLTAGE REGULATOR
X1 = parts:FPS009-300*: SD Card and MMC Reader (Manual Insertion) Source: http://www.yamaichi.de/pdf/c_fps009_3000.pdf; OC_FARNELL: unknown; OC_NEWARK: unknown
X2 = parts:MINI-USB-SHIELD-: MINI USB Connector Source: http://www.hirose.co.jp/cataloge_hp/e24000019.pdf; OC_FARNELL: unknown; OC_NEWARK: unknown
Y1 = parts:ECS-CRYSTAL
Y2 = parts:ABS25-CRYSTAL: CRYSTAL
